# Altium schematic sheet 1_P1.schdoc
size 307 x 218 mm; Symbol: Drawing-Symbol_A4; Device: Drawing-Symbol_A4; Company: 嘉立创EDA; Version: V1.0; Page Size: A4; @Project Name: 温度控制; @Page Count: 1; @Update Date: 2025-09-16; @Create Date: 2025-09-10; @Schematic Name: Schematic1; @Page No: 1; @Page Name: P1; @Create Time: 12:48:36; @Update Time: 21:52:46; Width: 1170; Height: 825; Region Start: 1; X Region Count: 6; Y Region Count: 4; Blade Width: 10; Title Block Position: 3; @Board Name: Board1
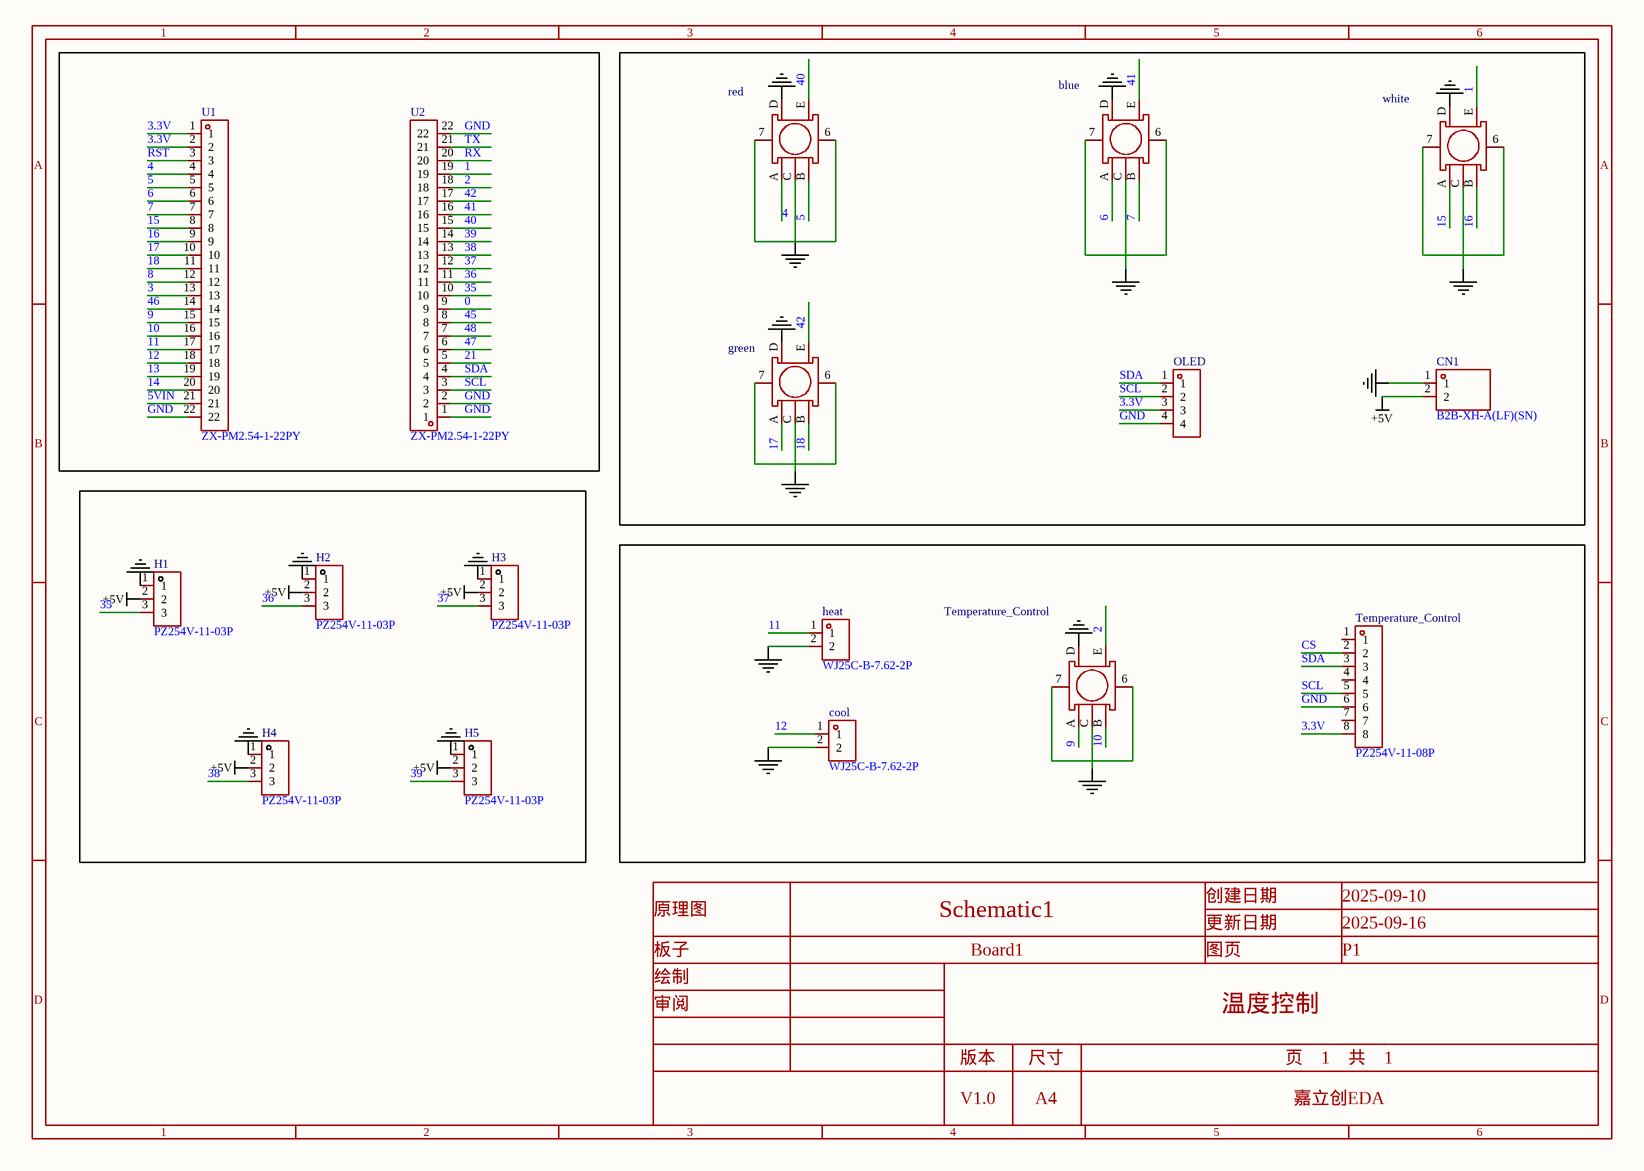
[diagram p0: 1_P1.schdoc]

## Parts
(Parts that share a designator on the sheet are numbered #1, #2 ... from top to bottom, then left to right.)
blue  EC11E15244G1  [SW-TH_EC11E15244G1]  (value not drawn)
CN1  B2B-XH-A(LF)(SN)  [CONN-TH_B2B-XH-A-LF-SN]
cool  WJ25C-B-7.62-2P  [CONN-TH_2P-P7.62_WJ25C-B-7.62-2P]
green  EC11E15244G1  [SW-TH_EC11E15244G1]  (value not drawn)
H1  PZ254V-11-03P  [HDR-TH_3P-P2.54-V-M]
H2  PZ254V-11-03P  [HDR-TH_3P-P2.54-V-M]
H3  PZ254V-11-03P  [HDR-TH_3P-P2.54-V-M]
H4  PZ254V-11-03P  [HDR-TH_3P-P2.54-V-M]
H5  PZ254V-11-03P  [HDR-TH_3P-P2.54-V-M]
heat  WJ25C-B-7.62-2P  [CONN-TH_2P-P7.62_WJ25C-B-7.62-2P]
OLED  (no value)  [HDR-TH_4P-P2.54-V-F]
red  5  [SW-TH_EC11E15244G1]  (value not drawn)
Temperature_Control#1  EC11E15244G1  [SW-TH_EC11E15244G1]  (value not drawn)
Temperature_Control#2  PZ254V-11-08P  [HDR-TH_8P-P2.54-V-M]
U1  ZX-PM2.54-1-22PY  [HDR-TH_22P-P2.54-V-F]
U2  ZX-PM2.54-1-22PY  [HDR-TH_22P-P2.54-V-F]
white  EC11E15244G1  [SW-TH_EC11E15244G1]  (value not drawn)

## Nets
+5V: CN1.2 H1.2 H2.2 H3.2 H4.2 H5.2
GND: blue.6 blue.7 blue.C blue.D CN1.1 cool.2 green.6 green.7 green.C green.D H1.1 H2.1 H3.1 H4.1 H5.1 heat.2 OLED.4 red.6 red.7 red.C red.D Temperature_Control#1.6 Temperature_Control#1.7 Temperature_Control#1.C Temperature_Control#1.D Temperature_Control#2.6 U1.22 U2.1 U2.2 U2.22 white.6 white.7 white.C white.D
0: U2.9
1: U2.19 white.E
2: Temperature_Control#1.E U2.18
3: U1.13
3.3V: OLED.3 Temperature_Control#2.8 U1.1 U1.2
4: red.A U1.4
5: red.B U1.5
5VIN: U1.21
6: blue.A U1.6
7: blue.B U1.7
8: U1.12
9: Temperature_Control#1.A U1.15
10: Temperature_Control#1.B U1.16
11: heat.1 U1.17
12: cool.1 U1.18
13: U1.19
14: U1.20
15: U1.8 white.A
16: U1.9 white.B
17: green.A U1.10
18: green.B U1.11
21: U2.5
35: H1.3 U2.10
36: H2.3 U2.11
37: H3.3 U2.12
38: H4.3 U2.13
39: H5.3 U2.14
40: red.E U2.15
41: blue.E U2.16
42: green.E U2.17
45: U2.8
46: U1.14
47: U2.6
48: U2.7
CS: Temperature_Control#2.2
RST: U1.3
RX: U2.20
SCL: OLED.2 Temperature_Control#2.5 U2.3
SDA: OLED.1 Temperature_Control#2.3 U2.4
TX: U2.21

Not connected (* = marked no-connect by the designer): Temperature_Control#2 1 4 7

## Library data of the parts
blue green red Temperature_Control#1 white = EC11E15244G1: Manufacturer: ALPSALPINE(阿尔卑斯阿尔派); Add into BOM: yes
CN1 = B2B-XH-A(LF)(SN): Manufacturer: JST; Add into BOM: yes; Pins Structure: 1x2P; Pitch: 2.5mm; Reference Series: XH; Number of PINs Per Row: 2; Current Rating: 3A; Voltage Rating: 250V; Plastic Material: PA66; Flame Retardant Rating: UL94V-0; Supplementary Features: 打K脚; Z-Height of the Board: 7mm; X-Length of Bottom Edge on Board (Spacing Line): 7.4mm; Y-Width of Bottom Edge on Board: 5.75mm
cool heat = WJ25C-B-7.62-2P: Manufacturer: KANGNEX(康奈克斯电气); Symbol: WJ25C-B-2P; Add into BOM: yes; Barrier Type: 两面; Pitch: 7.62mm; Number of Positions or Pins: 1x2P; Pin Location: 中脚; Number of PINs Per Row: 2; Current Rating: 24A; Voltage Rating (Max): 250V; Wire Gauge - AWG: 14~22; Wire Gauge - mm2: 2.5
H1-H5 = PZ254V-11-03P: Manufacturer: XFCN(兴飞); Symbol: PZ254V-11-03P_C2937625; Add into BOM: yes; Pin Structure: 1x3P; Pitch: 2.54mm; Circluar Pins/Square Pins: 方针; Current Rating: 3A; Voltage Rating (Max): 250V
OLED = HDR-F_2.54_1x4P: Symbol: 2.54-1*4P母; Convert to PCB: yes
Temperature_Control#2 = PZ254V-11-08P: Manufacturer: XFCN(兴飞); Add into BOM: yes; Pin Structure: 1x8P; Pitch: 2.54mm; Circluar Pins/Square Pins: 方针
U1 U2 = ZX-PM2.54-1-22PY: Manufacturer: Megastar(兆星); Add into BOM: yes; Holes Structure: 1x22P; Pitch: 2.54mm; Circular Hole / Square Hole: 方孔; Number of Positions: 22P; Current Rating: 3A; Holes Direction: 顶部; PIN Length: 3.2mm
